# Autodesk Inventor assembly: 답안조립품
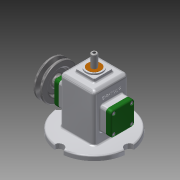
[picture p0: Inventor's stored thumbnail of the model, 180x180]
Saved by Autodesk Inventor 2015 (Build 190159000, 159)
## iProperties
Created: 2018-07
Part Number: 답안조립품
Document SubType Name: Assembly
Designer: pc
Author: pc
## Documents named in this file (15)
- C:\Users\pc\Desktop\480707V1016\답안조립품.iam
- C:\Users\pc\Desktop\480707V1016\본체.ipt
- C:\Users\pc\Desktop\480707V1016\뒤커버.ipt
- C:\Users\pc\Desktop\480707V1016\베어링 12x32x10.ipt
- C:\Users\pc\Desktop\480707V1016\볼트 M4.ipt
- C:\Users\pc\Desktop\480707V1016\앞커버.ipt
- C:\Users\pc\Desktop\480707V1016\오일 실 12 25 7.ipt
- C:\Users\pc\Desktop\480707V1016\V벨트풀리.ipt
- C:\Users\pc\Desktop\480707V1016\키 4x4x10.ipt
- C:\Users\pc\Desktop\480707V1016\편심축.ipt
- C:\Users\pc\Desktop\480707V1016\멈춤나사 M3x8.ipt
- C:\Users\pc\Desktop\480707V1016\슬라이드.ipt
- C:\Users\pc\Desktop\480707V1016\핀 5x18.ipt
- C:\Users\pc\Desktop\480707V1016\링크.ipt
- C:\Users\pc\Desktop\480707V1016\부시.ipt
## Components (2 placed, 2 different names)
1. V벨트풀리:1 — 각도:10
2. 핀 5x18:1
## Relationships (1: Angle 1)
- 각도:10 [Angle]: V벨트풀리:1
